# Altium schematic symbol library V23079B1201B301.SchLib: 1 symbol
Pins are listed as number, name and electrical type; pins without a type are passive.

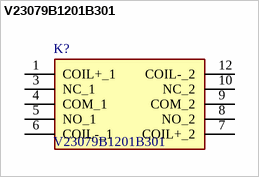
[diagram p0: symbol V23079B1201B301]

## V23079B1201B301
designator K?
TE CONNECTIVITY / AXICOM - V23079B1201B301 - RELAY, SIGNAL, DPDT, 250VAC, 220VDC, 2A; Geometry.Height: 9.9mm
footprint V23079B1201B301
pins: 1 COIL+_1, 3 NC_1, 4 COM_1, 5 NO_1, 6 COIL-_1, 7 COIL+_2, 8 NO_2, 9 COM_2, 10 NC_2, 12 COIL-_2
